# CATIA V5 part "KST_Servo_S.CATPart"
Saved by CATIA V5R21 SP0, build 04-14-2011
Part number: KST_Servo_S
Bounding box of the stored display mesh (mm): x -23.75 to 23.75, y -7.5 to 7.5, z 0 to 32.5
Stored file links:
  F:\教程\Robotic_Arm_Arduino_Kinect\机械臂CAD\Arm_Detailed_Design\KST_Servo_S.CATPart
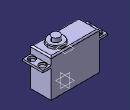
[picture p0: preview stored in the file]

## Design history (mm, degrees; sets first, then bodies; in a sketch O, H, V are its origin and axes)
Body1 (main body)
  Sketch1 on xy-plane, origin (0, 0, 0), H (1, 0, 0), V (0, 1, 0)
    line L1 (-17.75, 7.5) -> (17.75, 7.5)
    line L2 (17.75, 7.5) -> (17.75, -7.5)
    line L3 (17.75, -7.5) -> (-17.75, -7.5)
    line L4 (-17.75, -7.5) -> (-17.75, 7.5)
    length L1 = 35.5
    length L2 = 15
    distance H L1 = 7.5
    distance L2 V = 17.75
    horizontal: L1 H, L3 H
    vertical: L2 V, L4 V
  Pad1: profile Sketch1, direction (0, 0, 1), length 27.5
  Fillet1: radius 1, on end face of Pad1
  Sketch2 on end face of Pad1, origin (0, 0, 27.5), H (1, 0, 0), V (0, 1, 0)
    circle A1 centre (6.75, 0) radius 6
    point P1 (6.75, 0)
    reference projected line E1 (17.75, -7.5) -> (17.75, 7.5) from edge [face of Pad1 from Sketch1.L2 | face of Fillet1]
    radius A1 = 6
    distance P1 E1 = 11
    coincidence: P1 H
  Pad2: profile Sketch2, direction (0, 0, 1), length 2
  Sketch3 on end face of Pad2, origin (0, 0, 29.5), H (1, 0, 0), V (0, 1, 0)
    circle A1 centre (6.75, 0) radius 3
    point P1 (6.75, 0)
    reference projected circle E1 centre (6.75, 0) radius 6 from edge [end face of Pad1 | face of Pad2 from Sketch2.A1]
    radius A1 = 3
    coincidence: P1 H
    concentricity: P1 E1
  Pad3: profile Sketch3, direction (0, 0, 1), length 3
  Fillet2: radius 0.5, on edge [face of Pad2 from Sketch2.A1 | end face of Pad2]
  Plane1: type Offset, RefPlane end face of Pad1, Offset 7
  Sketch4 on Plane1, origin (0, 0, 20.5), H (1, 0, 0), V (0, -1, 0)
    point P1 (17.75, 7.5)
    line L1 (17.75, 7.5) -> (23.75, 7.5)
    line L2 (23.75, 7.5) -> (23.75, -7.5)
    line L3 (23.75, -7.5) -> (17.75, -7.5)
    line L4 (17.75, -7.5) -> (17.75, 7.5)
    point P2 (23.75, 7.5)
    point P3 (23.75, -7.5)
    point P4 (17.75, -7.5)
    reference projected line E1 (17.75, 7.5) -> (17.75, -7.5) from edge [start face of Pad1 | face of Pad1 from Sketch1.L2]
    reference projected line E2 (-17.75, 7.5) -> (17.75, 7.5) from edge [start face of Pad1 | face of Pad1 from Sketch1.L3]
    reference projected line E3 (17.75, -7.5) -> (-17.75, -7.5) from edge [start face of Pad1 | face of Pad1 from Sketch1.L1]
    circle A1 centre (20.5, 4) radius 2.5
    point P5 (20.5, 4)
    circle A2 centre (20.5, -4) radius 2.5
    point P6 (20.5, -4)
    point P7 (-17.75, 7.5)
    point P8 (-23.75, 7.5)
    point P9 (-23.75, -7.5)
    point P10 (-17.75, -7.5)
    line L5 (-17.75, 7.5) -> (-23.75, 7.5)
    line L6 (-23.75, 7.5) -> (-23.75, -7.5)
    line L7 (-23.75, -7.5) -> (-17.75, -7.5)
    line L8 (-17.75, -7.5) -> (-17.75, 7.5)
    circle A3 centre (-20.5, 4) radius 2.5
    circle A4 centre (-20.5, -4) radius 2.5
    distance L2 L4 = 6
    radius A2 = 2.5
    radius A1 = 2.5
    distance P5 P6 = 8
    distance P6 L3 = 3.5
    distance P5 V = 20.5
    distance P6 V = 20.5
    horizontal: L1 H, L3 H
    vertical: L2 V, L4 V
    coincidence: L4 E1, L1 E2, L3 E3
    symmetry: P1 P7 V, P2 P8 V, P3 P9 V, P4 P10 V, L1 L5 V, L2 L6 V, L3 L7 V, L4 L8 V, A1 A3 V, A2 A4 V
  Pad4: profile Sketch4, direction (0, 0, 1), length 1.5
